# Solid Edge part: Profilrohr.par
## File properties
Author: bmolnar
Last saved by: bmolnar
Revision: 77
Sűrűség: 0,000 kg/m^3
Pontosság: 0,990
Username: bmolnar
Dokumentum tartalom típus: 0
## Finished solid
Body 1: solid body, 63 faces, 178 edges, 112 vertices.
  Faces by surface: cylinder 33, plane 30
  Edges by curve: line 112, circle 66
Bounding box of the edges (mm): 36.000 x 18.400 x 36.000, from (-18, -9.15, -18) to (18, 9.25, 18).
Cylindrical faces by radius (mm): R0.2 x12, R0.5 x12, R3.775 x4, R4.5 x4, R10 x1
Planar faces by outward normal: +x 7, +y 1, +z 7, -x 7, -y 1, -z 7
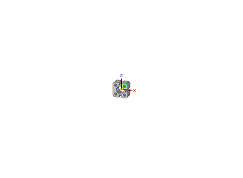
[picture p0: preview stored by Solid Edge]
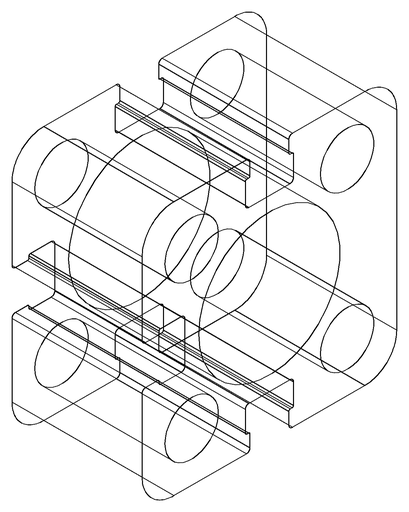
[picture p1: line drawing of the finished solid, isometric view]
